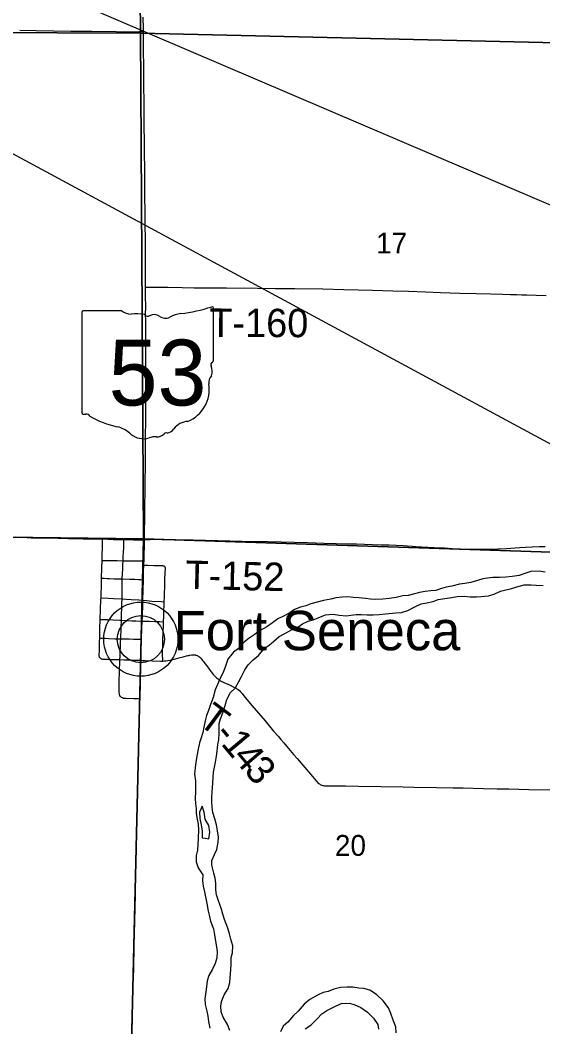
# Model space of a CAD drawing. Extents: x 0 to 34, y 0 to 22.
# Drawn here: x 4.194 to 4.718, y 18.765 to 19.773 of the extents above; entities that cross this region are included whole.
import ezdxf

# ---------------------------------------------------------------- set-up
doc = ezdxf.new("R2010")
doc.units = 0
for name, color, linetype in [('GM_X_Corporation', 7, 'Continuous'), ('GM_X_County_Road', 7, 'Continuous'), ('GM_X_Major_River', 7, 'Continuous'), ('GM_X_Section_Text', 7, 'Continuous'), ('GM_X_State_Location', 7, 'Continuous'), ('GM_X_State_Route', 7, 'Continuous'), ('GM_X_State_Shield', 7, 'Continuous'), ('GM_X_Township_Road', 7, 'Continuous'), ('GM_X_Township_Road_Text', 7, 'Continuous'), ('GM_X_Unincorporated', 7, 'Continuous'), ('GM_X_Unincorporated_Location', 7, 'Continuous'), ('GM_X_Unincorporated_Text', 7, 'Continuous'), ('SH_Text', 7, 'Continuous')]:
    doc.layers.add(name, color=color, linetype=linetype)

msp = doc.modelspace()

# ---------------------------------------------------------------- linework, layer by layer
at = {"layer": 'GM_X_Corporation'}
for points in [[(3.8116, 20.2678), (4.3097, 20.258), (4.3141, 19.7601), (3.8137, 19.7624)], [(4.8123, 20.246), (4.8186, 19.7484), (4.3141, 19.7601), (4.3097, 20.258)], [(4.3141, 19.7601), (4.3173, 19.2536), (3.8173, 19.2597), (3.8137, 19.7624)], [(4.8186, 19.7484), (4.8183, 19.2373), (4.3173, 19.2536), (4.3141, 19.7601)], [(3.8173, 19.2597), (4.3173, 19.2536), (4.3048, 18.7327), (3.8053, 18.7588)], [(4.3173, 19.2536), (4.8183, 19.2373), (4.8183, 19.2305), (4.8184, 19.1729), (4.8111, 19.1716), (4.8064, 19.1716), (4.8016, 19.172), (4.7978, 19.1736), (4.7913, 19.1754), (4.7827, 19.18), (4.7791, 19.1822), (4.7739, 19.1864), (4.7702, 19.1898), (4.7655, 19.1936), (4.7609, 19.1979), (4.7551, 19.2027), (4.7518, 19.2049), (4.7489, 19.2062), (4.7461, 19.2076), (4.7363, 18.7476), (4.561, 18.7477), (4.545, 18.7213), (4.3048, 18.7327)]]:
    msp.add_lwpolyline(points, close=True, dxfattribs=at)
at = {"layer": 'GM_X_County_Road'}
for points in [[(4.1932, 19.7631), (4.2097, 19.7628), (4.2445, 19.7623), (4.2653, 19.7621), (4.2898, 19.7618), (4.3023, 19.7617), (4.3129, 19.7619), (4.3171, 19.7619)], [(4.1886, 19.2554), (4.1961, 19.2551), (4.2045, 19.2547), (4.2215, 19.2544), (4.2417, 19.254), (4.2566, 19.2537), (4.2762, 19.2534)], [(4.2762, 19.2534), (4.2867, 19.253), (4.2977, 19.2528)], [(4.2977, 19.2528), (4.3023, 19.2528), (4.3073, 19.2527), (4.3117, 19.2526), (4.3183, 19.2526)]]:
    msp.add_lwpolyline(points, dxfattribs=at)
at = {"layer": 'GM_X_Major_River'}
for points in [[(4.7199, 19.2201), (4.7139, 19.2212), (4.7057, 19.2207), (4.6987, 19.2185), (4.6938, 19.2168), (4.6869, 19.2157), (4.6807, 19.2152)], [(4.6807, 19.2152), (4.6742, 19.2148), (4.6674, 19.2149), (4.6623, 19.2143), (4.6574, 19.2136), (4.6521, 19.2119), (4.6456, 19.2099), (4.6394, 19.2089), (4.634, 19.208), (4.6263, 19.206), (4.6208, 19.2051), (4.616, 19.2038), (4.6105, 19.2019), (4.6054, 19.2016), (4.5997, 19.2008), (4.594, 19.1999), (4.5891, 19.1986), (4.5825, 19.1969), (4.5773, 19.1964), (4.5705, 19.1947), (4.5637, 19.1938), (4.5572, 19.1931), (4.5498, 19.1928), (4.5449, 19.1932), (4.54, 19.1938), (4.533, 19.1944), (4.5277, 19.1948), (4.5215, 19.1956), (4.5165, 19.1952), (4.5101, 19.1943), (4.505, 19.1932), (4.4979, 19.1916), (4.485, 19.1884), (4.4799, 19.1865), (4.4748, 19.1851), (4.4687, 19.1828), (4.464, 19.1794), (4.4577, 19.176), (4.452, 19.1734), (4.4467, 19.1693), (4.4408, 19.1653), (4.4341, 19.1618), (4.4282, 19.1574), (4.4233, 19.1539), (4.4185, 19.1503), (4.4124, 19.1437), (4.4076, 19.1399), (4.4019, 19.1329), (4.3996, 19.1259), (4.3971, 19.1196), (4.3946, 19.1145), (4.3915, 19.1075), (4.3892, 19.1022), (4.3871, 19.0945), (4.3846, 19.0874), (4.3825, 19.0814), (4.3805, 19.0765), (4.3792, 19.0713), (4.3776, 19.0647), (4.3766, 19.0596), (4.3751, 19.0541), (4.3735, 19.049), (4.3722, 19.0429), (4.3706, 19.0359), (4.3698, 19.0295), (4.369, 19.0243), (4.3684, 19.0177), (4.3693, 19.0112), (4.3695, 19.0063), (4.3693, 19.0004), (4.369, 18.993), (4.3694, 18.9883), (4.3701, 18.9831), (4.3699, 18.9784), (4.3712, 18.9725), (4.3721, 18.9677), (4.3724, 18.9621), (4.372, 18.9535), (4.3718, 18.9472), (4.3714, 18.9417), (4.3702, 18.9361), (4.3701, 18.93), (4.3722, 18.9239), (4.3767, 18.917), (4.3765, 18.9108), (4.377, 18.9055), (4.3783, 18.8999), (4.3794, 18.895), (4.3807, 18.888), (4.382, 18.8806), (4.3834, 18.8752), (4.3845, 18.8705), (4.3873, 18.8629), (4.3884, 18.8568), (4.3895, 18.8505), (4.3906, 18.8448), (4.391, 18.8397), (4.3909, 18.8338), (4.3892, 18.8281), (4.3863, 18.8223), (4.3827, 18.816)], [(4.4037, 18.8091), (4.4041, 18.814), (4.4049, 18.8218), (4.4051, 18.8275), (4.4051, 18.8341), (4.4065, 18.8388), (4.4067, 18.8457), (4.4047, 18.8523), (4.4036, 18.8577), (4.4019, 18.8636), (4.3986, 18.8721), (4.3969, 18.8776), (4.3954, 18.8824), (4.3921, 18.8919), (4.3904, 18.8968), (4.3899, 18.9018), (4.3899, 18.9086), (4.389, 18.9137), (4.3877, 18.9185), (4.3858, 18.9265), (4.3857, 18.9312), (4.3886, 18.9373), (4.3907, 18.9424), (4.3922, 18.9496), (4.3925, 18.9547), (4.3914, 18.9608), (4.3903, 18.9671), (4.3888, 18.973), (4.3867, 18.9794), (4.3862, 18.9846), (4.3859, 18.9901), (4.3859, 18.9948), (4.3861, 19.0001), (4.3869, 19.0088), (4.3872, 19.0145), (4.3876, 19.0197), (4.3884, 19.0246), (4.3893, 19.0299), (4.3903, 19.0358), (4.3911, 19.0407), (4.3917, 19.0474), (4.3927, 19.0521), (4.3931, 19.0587), (4.3932, 19.0686), (4.3945, 19.0733), (4.3968, 19.0792), (4.399, 19.0864), (4.4009, 19.0927), (4.4044, 19.0997), (4.4091, 19.104), (4.413, 19.1106), (4.4154, 19.1156), (4.4187, 19.1222), (4.4223, 19.1273), (4.4271, 19.1324), (4.4326, 19.1367), (4.4382, 19.1437), (4.4431, 19.1469), (4.4479, 19.151), (4.4532, 19.1556), (4.4591, 19.1586), (4.4656, 19.1623), (4.4705, 19.164), (4.4766, 19.1683), (4.4825, 19.171), (4.4874, 19.1725), (4.4923, 19.1745), (4.4996, 19.1775), (4.5073, 19.178), (4.5134, 19.1772), (4.5206, 19.1764), (4.5253, 19.1772), (4.5306, 19.1777), (4.5359, 19.1777), (4.5414, 19.1773), (4.5477, 19.1774), (4.5535, 19.1779), (4.5598, 19.1783), (4.5704, 19.1794), (4.5759, 19.1799), (4.5822, 19.1818), (4.5892, 19.1855), (4.5958, 19.1885), (4.6015, 19.1894), (4.6078, 19.1907), (4.6127, 19.1926), (4.6194, 19.1939), (4.6264, 19.1948), (4.6319, 19.1959), (4.6389, 19.1962), (4.6448, 19.1956), (4.651, 19.1956), (4.6559, 19.1959), (4.6631, 19.1963), (4.6696, 19.1983), (4.6751, 19.201), (4.6804, 19.2023), (4.6853, 19.2034), (4.6916, 19.2056), (4.699, 19.2073), (4.7058, 19.2076)], [(4.7058, 19.2076), (4.7111, 19.2072), (4.7181, 19.2068)], [(4.376, 18.9858), (4.3733, 18.9797), (4.3736, 18.9732), (4.3751, 18.967), (4.376, 18.9605), (4.3762, 18.9541), (4.3791, 18.9536)], [(4.3791, 18.9536), (4.3826, 18.9531), (4.3836, 18.9595), (4.3827, 18.9662), (4.3791, 18.9728), (4.378, 18.9797), (4.376, 18.9858)], [(4.3827, 18.816), (4.3811, 18.8105), (4.3805, 18.8048), (4.3796, 18.7997), (4.3789, 18.7927), (4.3791, 18.7868), (4.3808, 18.7802), (4.3817, 18.7754), (4.3824, 18.7699), (4.3839, 18.7634)], [(4.4037, 18.761), (4.4015, 18.7669), (4.397, 18.7744), (4.395, 18.7795), (4.3948, 18.7852), (4.3956, 18.7901), (4.3981, 18.7968), (4.4023, 18.803), (4.4037, 18.8091)], [(4.5706, 18.7587), (4.5701, 18.7646), (4.5675, 18.7713), (4.5652, 18.7779), (4.5628, 18.7836), (4.5577, 18.7905), (4.5508, 18.797), (4.5443, 18.8012), (4.5381, 18.803), (4.5332, 18.8034), (4.5273, 18.8042), (4.5213, 18.8042), (4.5148, 18.804), (4.5082, 18.8022), (4.5025, 18.8001), (4.4975, 18.799), (4.4917, 18.7964), (4.4841, 18.7919), (4.4783, 18.7874), (4.4724, 18.7804), (4.4675, 18.776), (4.4619, 18.7691), (4.4572, 18.7651), (4.4545, 18.7596)], [(4.4793, 18.7627), (4.485, 18.7664), (4.4915, 18.7725), (4.4959, 18.7776), (4.501, 18.7808), (4.5058, 18.7832), (4.5105, 18.7855), (4.5157, 18.7881), (4.5234, 18.7884), (4.5285, 18.7871), (4.5351, 18.784), (4.5419, 18.7792), (4.5478, 18.7731), (4.5521, 18.767), (4.5528, 18.7622)]]:
    msp.add_lwpolyline(points, dxfattribs=at)
at = {"layer": 'GM_X_State_Route'}
for points in [[(4.3189, 19.3104), (4.3191, 19.3273), (4.3192, 19.3397), (4.3194, 19.3562), (4.3195, 19.372), (4.3196, 19.3885), (4.3196, 19.3965), (4.3196, 19.4031), (4.3196, 19.4173), (4.3196, 19.4216), (4.3196, 19.4315), (4.3197, 19.4365), (4.3196, 19.4436), (4.3196, 19.4488), (4.3195, 19.4569), (4.3195, 19.4634), (4.3195, 19.4708), (4.3194, 19.4801), (4.3195, 19.4844), (4.3192, 19.4984), (4.3192, 19.5058), (4.3191, 19.5419), (4.3191, 19.5549), (4.319, 19.5668), (4.3188, 19.5804), (4.3186, 19.5975), (4.3185, 19.6087), (4.3185, 19.6264), (4.3184, 19.6379), (4.3182, 19.6553), (4.318, 19.6637), (4.3179, 19.6724), (4.3178, 19.682), (4.3178, 19.6907), (4.3177, 19.7081), (4.3176, 19.7199), (4.3176, 19.724), (4.3174, 19.7457), (4.3171, 19.7619), (4.3171, 19.7647), (4.3168, 19.7762)], [(4.3128, 19.0596), (4.3129, 19.0643), (4.3135, 19.0863), (4.3137, 19.0931), (4.3141, 19.1044), (4.3144, 19.1157), (4.3146, 19.1205), (4.3147, 19.126), (4.3148, 19.1317), (4.315, 19.1412), (4.3152, 19.1523), (4.3153, 19.1529), (4.3157, 19.1641), (4.3159, 19.1711), (4.3161, 19.1762), (4.3165, 19.1876), (4.3167, 19.192), (4.3172, 19.2125), (4.3174, 19.2207), (4.3176, 19.2267), (4.3177, 19.2289), (4.3178, 19.2314), (4.318, 19.239), (4.3182, 19.2453), (4.3183, 19.2526), (4.3184, 19.264), (4.3185, 19.2708), (4.3187, 19.2873), (4.3188, 19.3006), (4.3189, 19.3099), (4.3189, 19.3104)], [(4.3059, 18.7575), (4.3063, 18.7758), (4.307, 18.8063), (4.3075, 18.8227), (4.308, 18.8464), (4.3083, 18.8576), (4.3089, 18.8837), (4.3091, 18.8964), (4.3093, 18.9036), (4.3096, 18.9154), (4.3097, 18.9259), (4.31, 18.9413), (4.3104, 18.9534), (4.3106, 18.964), (4.3107, 18.9702), (4.3109, 18.9776), (4.3113, 18.9978), (4.3117, 19.013), (4.3118, 19.0177), (4.3119, 19.0255), (4.3122, 19.0394), (4.3127, 19.0565), (4.3128, 19.0596)]]:
    msp.add_lwpolyline(points, dxfattribs=at)
at = {"layer": 'GM_X_State_Shield'}
for p, q in [((4.2555, 19.4802), (4.2555, 19.3802)), ((4.2954, 19.4819), (4.2568, 19.4819)), ((4.3874, 19.4321), (4.3874, 19.4844)), ((4.3873, 19.4321), (4.3874, 19.4321))]:
    msp.add_line(p, q, dxfattribs=at)
for centre, radius, start, end in [((4.257, 19.4804), 0.00153, 98.1301, 188.1301), ((4.3046, 19.4936), 0.0148, 231.6195, 271.1119), ((4.3582, 19.4514), 0.0281, 97.3462, 120.7689), ((4.3404, 19.6184), 0.1398, 275.8445, 288.9065), ((4.3859, 19.4846), 0.00147, 351.8621, 97.738), ((4.3095, 19.4258), 0.0532, 80.4867, 94.9883), ((4.3216, 19.481), 0.00427, 219.7921, 297.1024), ((4.3279, 19.4694), 0.00889, 54.4667, 119.1411), ((4.3393, 19.4853), 0.0107, 233.8562, 294.8282), ((4.387, 19.4282), 0.00227, 107.944, 210.337), ((4.3858, 19.4319), 0.00157, 289.6038, 7.7341), ((4.3726, 19.4216), 0.0136, 340.033, 23.6496), ((4.3482, 19.4035), 0.035, 292.3089, 8.9858), ((4.3926, 19.4102), 0.00992, 136.8065, 186.9296), ((4.257, 19.3799), 0.00154, 171.9584, 258.3066), ((4.2573, 19.3902), 0.0118, 267.339, 280.6039), ((4.2597, 19.3744), 0.00424, 29.7484, 93.2717), ((4.3132, 19.4643), 0.101, 240.4129, 257.1985), ((4.363, 19.3521), 0.0192, 94.4031, 142.5768), ((4.2831, 19.3352), 0.0316, 47.1842, 75.836), ((4.3173, 19.3739), 0.02, 230.7004, 286.2918), ((4.3303, 19.3664), 0.0107, 268.777, 315.5493), ((4.34, 19.3567), 0.00301, 65.7517, 132.6484), ((4.3387, 19.3705), 0.0113, 282.8732, 323.2771), ((4.3289, 19.3393), 0.0165, 85.6951, 111.2099)]:
    msp.add_arc(centre, radius, start, end, dxfattribs=at)
at = {"layer": 'GM_X_Township_Road'}
for points in [[(4.3192, 19.5058), (4.3235, 19.5058), (4.3315, 19.5057), (4.3417, 19.5056), (4.3561, 19.5054), (4.3679, 19.5052), (4.3766, 19.5051), (4.4005, 19.5049), (4.4316, 19.5047), (4.4496, 19.5045), (4.4689, 19.5043), (4.4972, 19.5039), (4.518, 19.5034), (4.5469, 19.5026), (4.5671, 19.502), (4.5829, 19.5016), (4.6, 19.501), (4.6149, 19.5005), (4.6345, 19.4998), (4.6513, 19.4994), (4.6655, 19.499), (4.6774, 19.4987), (4.6854, 19.4985), (4.6913, 19.4983), (4.6966, 19.4982), (4.7016, 19.498), (4.7109, 19.4977), (4.7211, 19.4974)], [(4.1886, 19.2554), (4.1961, 19.2551), (4.2045, 19.2547), (4.2215, 19.2544), (4.2417, 19.254), (4.2566, 19.2537), (4.2762, 19.2534)], [(4.2757, 19.2318), (4.2759, 19.2382), (4.2761, 19.244), (4.2762, 19.2493), (4.2762, 19.2534)], [(4.2762, 19.2534), (4.2867, 19.253), (4.2977, 19.2528)], [(4.2968, 19.2316), (4.297, 19.2359), (4.2972, 19.2397), (4.2974, 19.2452), (4.2976, 19.2502), (4.2977, 19.2528)], [(4.2977, 19.2528), (4.3023, 19.2528), (4.3073, 19.2527), (4.3117, 19.2526), (4.3183, 19.2526)], [(4.3183, 19.2526), (4.3238, 19.2529), (4.3307, 19.2531), (4.3361, 19.253), (4.3402, 19.253), (4.3445, 19.2529), (4.3492, 19.2528), (4.367, 19.2524), (4.3919, 19.2518), (4.4159, 19.2513), (4.4419, 19.2508), (4.4817, 19.2498), (4.498, 19.2493), (4.5103, 19.2489), (4.5218, 19.2486), (4.5308, 19.2484), (4.5468, 19.248), (4.5551, 19.2477), (4.5636, 19.2475), (4.5776, 19.2468), (4.5865, 19.2463), (4.5908, 19.246), (4.5961, 19.2457), (4.6087, 19.245), (4.6189, 19.2444), (4.6304, 19.2436), (4.6346, 19.2434), (4.6397, 19.2432), (4.6475, 19.2431), (4.654, 19.2431), (4.6611, 19.2431), (4.6674, 19.2433), (4.6726, 19.2435), (4.6808, 19.2439), (4.6947, 19.2448), (4.7002, 19.2452), (4.707, 19.2456), (4.7143, 19.2458), (4.7199, 19.2458)], [(4.2752, 19.2142), (4.2755, 19.2243), (4.2757, 19.2318)], [(4.2757, 19.2318), (4.281, 19.2318), (4.2859, 19.2317), (4.2909, 19.2317), (4.2968, 19.2316)], [(4.2959, 19.2134), (4.2962, 19.2184), (4.2965, 19.2236), (4.2967, 19.2277), (4.2968, 19.2316)], [(4.2968, 19.2316), (4.3005, 19.2316), (4.3047, 19.2316), (4.3082, 19.2316), (4.3111, 19.2316), (4.3134, 19.2316), (4.3154, 19.2315), (4.3178, 19.2314)], [(4.338, 19.1905), (4.3382, 19.1952), (4.3386, 19.2092), (4.3388, 19.2139), (4.3392, 19.224), (4.3392, 19.2244), (4.3391, 19.2247), (4.3389, 19.2253), (4.3385, 19.2257), (4.338, 19.226), (4.3375, 19.2262), (4.3371, 19.2263), (4.3368, 19.2264), (4.3363, 19.2264), (4.3356, 19.2265), (4.3279, 19.2266), (4.3216, 19.2267), (4.3176, 19.2267)], [(4.2747, 19.1945), (4.2748, 19.1993), (4.275, 19.205), (4.2751, 19.2106), (4.2752, 19.2142)], [(4.2752, 19.2142), (4.2777, 19.214), (4.2808, 19.2138), (4.2832, 19.2138), (4.2878, 19.2136), (4.2897, 19.2135), (4.2921, 19.2135), (4.2959, 19.2134)], [(4.2957, 19.1934), (4.2958, 19.2005), (4.2959, 19.2084), (4.2959, 19.2114), (4.2959, 19.2134)], [(4.2959, 19.2134), (4.3037, 19.2133), (4.3062, 19.2132), (4.3087, 19.2131), (4.3119, 19.2129), (4.3146, 19.2127), (4.3172, 19.2125)], [(4.2739, 19.1728), (4.2743, 19.1827), (4.2746, 19.1929), (4.2747, 19.1945)], [(4.2747, 19.1945), (4.2821, 19.1941), (4.2873, 19.1939), (4.2957, 19.1934)], [(4.2951, 19.1719), (4.2951, 19.1738), (4.2955, 19.1884), (4.2957, 19.1934)], [(4.2957, 19.1934), (4.2998, 19.1931), (4.305, 19.1928), (4.3127, 19.1923), (4.3167, 19.192)], [(4.3167, 19.192), (4.3202, 19.1916), (4.3257, 19.1912), (4.3351, 19.1906), (4.338, 19.1905)], [(4.3374, 19.1705), (4.3376, 19.176), (4.3377, 19.1813), (4.3379, 19.1868), (4.338, 19.1905)], [(4.2734, 19.1542), (4.2736, 19.1634), (4.2739, 19.1728)], [(4.2739, 19.1728), (4.2764, 19.1727), (4.281, 19.1726), (4.2867, 19.1724), (4.2934, 19.172), (4.2951, 19.1719)], [(4.2945, 19.1533), (4.2949, 19.1646), (4.2951, 19.1719)], [(4.2951, 19.1719), (4.3003, 19.1717), (4.3055, 19.1715), (4.3097, 19.1713), (4.3159, 19.1711)], [(4.3159, 19.1711), (4.323, 19.1709), (4.3286, 19.1708), (4.3333, 19.1706), (4.3374, 19.1705)], [(4.3366, 19.1311), (4.3364, 19.1386), (4.3364, 19.1423), (4.3365, 19.1448), (4.3367, 19.1531), (4.337, 19.159), (4.3373, 19.1676), (4.3374, 19.1705)], [(4.274, 19.134), (4.2735, 19.1344), (4.2732, 19.1348), (4.273, 19.1353), (4.2729, 19.1359), (4.2728, 19.1363), (4.2728, 19.1369), (4.273, 19.1417), (4.2732, 19.1501), (4.2734, 19.1542)], [(4.2734, 19.1542), (4.2745, 19.1541), (4.2787, 19.1539), (4.2824, 19.1536), (4.2886, 19.1534), (4.2945, 19.1533)], [(4.2935, 19.1322), (4.2937, 19.1361), (4.2939, 19.1406), (4.2941, 19.1449), (4.2943, 19.1503), (4.2945, 19.1533)], [(4.2945, 19.1533), (4.2985, 19.1533), (4.3028, 19.1532), (4.3072, 19.1531), (4.31, 19.153), (4.3121, 19.153), (4.3153, 19.1529)], [(4.3366, 19.1311), (4.3383, 19.1312), (4.3397, 19.1314), (4.3436, 19.1321), (4.3466, 19.1328), (4.3494, 19.1334), (4.3539, 19.1346), (4.3571, 19.1354), (4.3605, 19.1363), (4.3616, 19.1366), (4.3631, 19.1368), (4.3637, 19.137), (4.3653, 19.1372), (4.3661, 19.1373), (4.3667, 19.1373), (4.3678, 19.1373), (4.3683, 19.1373), (4.3693, 19.1372), (4.3697, 19.1371), (4.3708, 19.1368), (4.3713, 19.1366), (4.3722, 19.1361), (4.3726, 19.1358), (4.3737, 19.1349), (4.3746, 19.1339), (4.3757, 19.1327), (4.3764, 19.1318), (4.3775, 19.1306), (4.3789, 19.1287), (4.3806, 19.1263), (4.3831, 19.1228), (4.3841, 19.1216), (4.3847, 19.1207), (4.3854, 19.1198), (4.3865, 19.1185), (4.3872, 19.1177), (4.3879, 19.1169), (4.3887, 19.116), (4.3895, 19.1153), (4.3906, 19.1144), (4.3913, 19.1137), (4.3923, 19.1129), (4.3929, 19.1124), (4.3936, 19.1119), (4.3943, 19.1114), (4.3952, 19.111), (4.3978, 19.1097), (4.4034, 19.1071), (4.4079, 19.105), (4.4089, 19.1045), (4.4098, 19.1041), (4.411, 19.1034), (4.4122, 19.1025), (4.4134, 19.1015)], [(4.2935, 19.1322), (4.29, 19.1323), (4.2851, 19.1324), (4.281, 19.1325), (4.2781, 19.1325), (4.2776, 19.1326), (4.2772, 19.1326), (4.2769, 19.1326), (4.2765, 19.1327), (4.2758, 19.1329), (4.2753, 19.1331), (4.2748, 19.1334), (4.2744, 19.1337), (4.274, 19.134)], [(4.3137, 19.0931), (4.3098, 19.0931), (4.3076, 19.0932), (4.2995, 19.0934), (4.2984, 19.0935), (4.2973, 19.0937), (4.2961, 19.0941), (4.2951, 19.0945), (4.2944, 19.0951), (4.2939, 19.0957), (4.2936, 19.0965), (4.2933, 19.0973), (4.2932, 19.0981), (4.293, 19.0997), (4.2929, 19.1019), (4.2929, 19.1078), (4.293, 19.1112), (4.2932, 19.1199), (4.2935, 19.1322)], [(4.3148, 19.1317), (4.3081, 19.1318), (4.3049, 19.1319), (4.3013, 19.132), (4.2978, 19.1321), (4.2935, 19.1322)], [(4.3148, 19.1317), (4.3188, 19.1316), (4.326, 19.1313), (4.3345, 19.131), (4.3366, 19.1311)], [(4.4134, 19.1015), (4.4144, 19.1003), (4.4161, 19.0985), (4.4179, 19.0964), (4.426, 19.0867), (4.4392, 19.0711), (4.4477, 19.0609), (4.4522, 19.0558), (4.455, 19.0525), (4.4578, 19.0492), (4.461, 19.0455), (4.4644, 19.0415), (4.4677, 19.0376), (4.4714, 19.0333), (4.4789, 19.0245), (4.4905, 19.0109), (4.4921, 19.0092), (4.4929, 19.0085), (4.4936, 19.0079), (4.4944, 19.0075), (4.4951, 19.0071), (4.4959, 19.0067), (4.4969, 19.0064), (4.4978, 19.0063), (4.4988, 19.0062), (4.5, 19.0062), (4.5011, 19.0062), (4.5128, 19.006), (4.5198, 19.0059), (4.5329, 19.0057), (4.5776, 19.0049), (4.5882, 19.0047), (4.6111, 19.0044), (4.6276, 19.004), (4.6378, 19.0039), (4.6581, 19.0035), (4.672, 19.0032), (4.6835, 19.0029), (4.7037, 19.0025), (4.7286, 19.0021)]]:
    msp.add_lwpolyline(points, dxfattribs=at)
at = {"layer": 'GM_X_Unincorporated'}
for radius in [0.0372, 0.0236]:
    msp.add_circle((4.3146, 19.153), radius, dxfattribs=at)
at = {"layer": 'GM_X_Unincorporated_Location'}
msp.add_line((4.3146, 19.153), (4.3146, 19.153), dxfattribs=at)
at = {"layer": 'SH_Text'}
msp.add_lwpolyline([(9.297, 16.882), (2.5966, 20.4971), (9.297, 17.6363)], close=True, dxfattribs=at)

# ---------------------------------------------------------------- texts
at = {"layer": 'GM_X_Section_Text'}
for s, p in [('17', (4.5505, 19.5395)), ('20', (4.5092, 18.9359))]:
    msp.add_text(s, height=0.02093, rotation=0, dxfattribs=at).set_placement(p)
at = {"layer": 'GM_X_State_Location'}
for s, p in [('s', (4.32, 19.4235)), ('r', (4.3199, 19.4235))]:
    msp.add_text(s, height=0.0000947, dxfattribs=at).set_placement(p)
msp.add_text('53', height=0.0000947, rotation=0, dxfattribs=at).set_placement((4.2961, 19.4167))
at = {"layer": 'GM_X_State_Shield'}
msp.add_text('53', height=0.06592, dxfattribs=at).set_placement((4.2823, 19.3872))
at = {"layer": 'GM_X_Township_Road_Text'}
for s, height, rotation, p in [('T-160', 0.02841, 359.7194, (4.3832, 19.456)), ('T-152', 0.02841, 358.6169, (4.359, 19.2035)), ('T', 0.0284, 323.3478, (4.3708, 19.0685)), ('-', 0.0284, 309.9265, (4.3866, 19.057)), ('1', 0.0284, 309.9316, (4.3941, 19.0481)), ('4', 0.0284, 310.2991, (4.4055, 19.0345)), ('3', 0.0284, 311.1188, (4.4171, 19.0208))]:
    msp.add_text(s, height=height, rotation=rotation, dxfattribs=at).set_placement(p)
at = {"layer": 'GM_X_Unincorporated_Text'}
msp.add_text('Fort Seneca', height=0.039489, rotation=0, dxfattribs=at).set_placement((4.3474, 19.1419))

doc.saveas('drawing.dxf')
